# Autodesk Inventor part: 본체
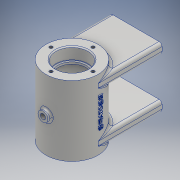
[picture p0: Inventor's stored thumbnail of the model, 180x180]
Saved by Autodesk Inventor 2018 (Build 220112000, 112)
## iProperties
Created: 2020-07
Part Number: 본체
Material: 알루미늄 6061
Document SubType Name: Modeling
Designer: home
Density: 2.7 g/cm^3
Appearance: 알루미늄 - 평지
Mass: 305.056 g
Surface Area: 358.163 cm^2
Volume: 112.984 cm^3
Author: home
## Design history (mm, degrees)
sketch "스케치1"
  geometry: L1 (16, 35)-(16, 23); L2 (16, 23)-(14, 23); L3 (14, 23)-(14, 21); L4 (14, 21)-(21, 21); L5 (21, 21)-(21, -21); L6 (21, -21)-(14, -21); L7 (14, -21)-(14, -23); L8 (14, -23)-(16, -23); L9 (16, -23)-(16, -35); L10 (0, -35)-(0, 35); L11 (16, 35)-(26, 35); L12 (26, 35)-(26, -35); L13 (26, -35)-(16, -35); 3 further points
  constraints: 26 end point, 8 perpendicular, 2 coincident, 2 horizontal, 2 point on line, 2 vertical, 1 midpoint
  dimensions: "d2" = 2 distance of L2.end L3.end; "d4" = 42 distance of L4.end L5.end; "d5" = 2 distance of L6.end L7.end; "d6" = 12 distance of L8.end L9.end; "d8" = 70 distance of L10.start L10.end; "d11" = 32 diameter of L1 L10; "d12" = 52 diameter of L12 L10; "d13" = 42 diameter of L5 L10; "d14" = 10 distance of L12.end L9.end; "d15" = 2 distance of L7.end L8.end; "d16" = 70 distance between parallel lines of L13 L11; "d17" = 35 distance from line of point (0, 0) L11
revolve "회전1" sketch "스케치1" stored, may be unused: angle "d18" = 90 deg
node "작업 평면1"
sketch "스케치2"
  geometry: 1 further point
sketch "스케치3"
  geometry: L1 (-26, -30)-(26, -30); L2 (26, -30)-(26, -20); L3 (26, -20)-(-26, -20); L4 (-26, -20)-(-26, -30); L5 (-26, 35)-(26, 35) reference; L6 (-26, -35)-(26, -35) reference; L7 (-26, 35)-(-26, -35) reference; 1 further point
  constraints: 8 end point, 2 parallel, 1 horizontal, 1 perpendicular
  dimensions: "d20" = 52 distance of L3.end L2.end; "d21" = 10 distance of L2.end L1.end; "d22" = 20 distance from line of L3 point (0, 0); "d23" = 0 distance between parallel lines of L4 L7
extrude "돌출1" join sketch "스케치3" stored distance "d24" = 10; taper "d25" = 0 deg
sketch "스케치4" dims "d26" = 42
  geometry: 3 further points
  constraints: 2 vertical alignment, 1 coincident, 2 other
  dimensions: "d88" = 21 distance of point (0, -21) point (0, 0) (derived)
hole "구멍1" sketch "스케치4" at (0, -21) diameter "d27" = 3.242; stored, may be unused: countersink angle "d31" = 90 deg, drill point angle "d33" = 118 deg; dims "d28" = 8, "d29" = 4, "d30" = 2, "d32" = 10
node "작업 평면2"
sketch "스케치6"
  geometry: C1 r 5 at (0, 0); 1 further point
  constraints: 1 centre point, 1 coincident
  dimensions: "d38" = 10 diameter of C1
extrude "돌출2" join sketch "스케치6" stored distance "d39" = 10 (= d38); taper "d40" = 0 deg
sketch "스케치7"
  geometry: 1 further point
hole "구멍2" sketch "스케치7" at (0, 0) diameter "d41" = 5.188; stored, may be unused: countersink angle "d45" = 90 deg, drill point angle "d47" = 118 deg; dims "d42" = 12, "d43" = 4, "d44" = 2, "d46" = 16
node "작업 평면4"
sketch "스케치11"
  geometry: L1 (-26, -35)-(26, -35) reference; L2 (0, -14.175)-(0, -3.309); L3 (0, -3.309)-(36.054, -3.309); L4 (36.054, -3.309)-(36.054, -14.175); L5 (36.054, -14.175)-(0, -14.175); 1 further point
  constraints: 1 vertical, 2 other
  dimensions: "d53" = 35 distance from line of L1 point (0, 0) (derived); "d54" = 26 horizontal distance of L2.end L1.start; "d89" = 31.69099 distance between parallel lines of L1 L3; "d90" = 20.82547 distance between parallel lines of L1 L5; "d91" = 36.05377 distance between parallel lines of L4 L2
feature "엠보싱1" sketch "스케치11" dims "d20" = 52, "d21" = 10, "d22" = 20, "d23" = 0, "d55" = 1, "d56" = 0
fillet "모깎기1" dims "d57" = 3, "d58" = 3, "d59" = 3, "d60" = 0.3, "d81" = 2
chamfer "모따기1" distance "d62" = 1; stored, may be unused: second distance "d63" = 2, angle "d64" = 45 deg
sketch "스케치12"
  geometry: 2 further points
  dimensions: "d65" = 20 horizontal distance of point (3, 5) point (23, 30); "d92" = 32.01562 distance of point (3, 5) point (23, 30)
hole "구멍3" sketch "스케치12" at (3, 5) diameter "d66" = 4.134; stored, may be unused: countersink angle "d70" = 90 deg, drill point angle "d72" = 118 deg; dims "d67" = 8, "d68" = 4, "d69" = 2, "d71" = 10
sketch "스케치14"
  geometry: C1 r 5 at (0, 0); C2 r 6 at (0, 0); 1 further point
  constraints: 2 centre point, 2 coincident
  dimensions: "d82" = 10 diameter of C1; "d83" = 12 diameter of C2
extrude "돌출3" join sketch "스케치14" stored distance "d84" = 10; taper "d85" = 0 deg
fillet "모깎기2" dims "d87" = 2
node "솔리드1"
mirror "미러1"
pattern_circular "원형 패턴1" dims angle "d35" = 360 deg
mirror "미러2"
pattern_circular "원형 패턴2" dims angle "d49" = 160 deg
pattern_linear "직사각형 패턴1" dims "d75" = 40, "d78" = 50
node "투영된 루프1"
other parameters: "d19" = 64, "d37" = -29, "d52" = 26
